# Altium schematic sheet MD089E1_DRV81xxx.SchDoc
size 431 x 279 mm; Date: Not shown in title block; ApprovedBy: Not shown in title block; CheckedBy: Not shown in title block; Author: Not shown in title block; CompanyName: Not shown in title block; DrawnBy: Tilden Chen; Engineer: Not shown in title block; Organization: Not shown in title block; Address1: Not shown in title block; Address2: Not shown in title block; Address3: Not shown in title block; Address4: Not shown in title block; DocumentNumber: 2; Revision: Use project parameter SCH_Rev; SheetNumber: 2; SheetTotal: 3; PageSetup: Record=PageOptions¦CenterHorizontal=True¦CenterVertical=True¦PrintScale=1.00¦XCorrection=1.00¦YCorrection=1.00¦PrintKind=0¦BorderSize=5000000¦LeftOffset=0¦BottomOffset=0¦Orientation=2¦PaperLength=1000¦PaperWidth=1000¦Scale=100¦PaperSource=15¦PrintQuality=600¦MediaType=1¦DitherType=10¦PaperKind=Letter¦PrintScaleMode=1
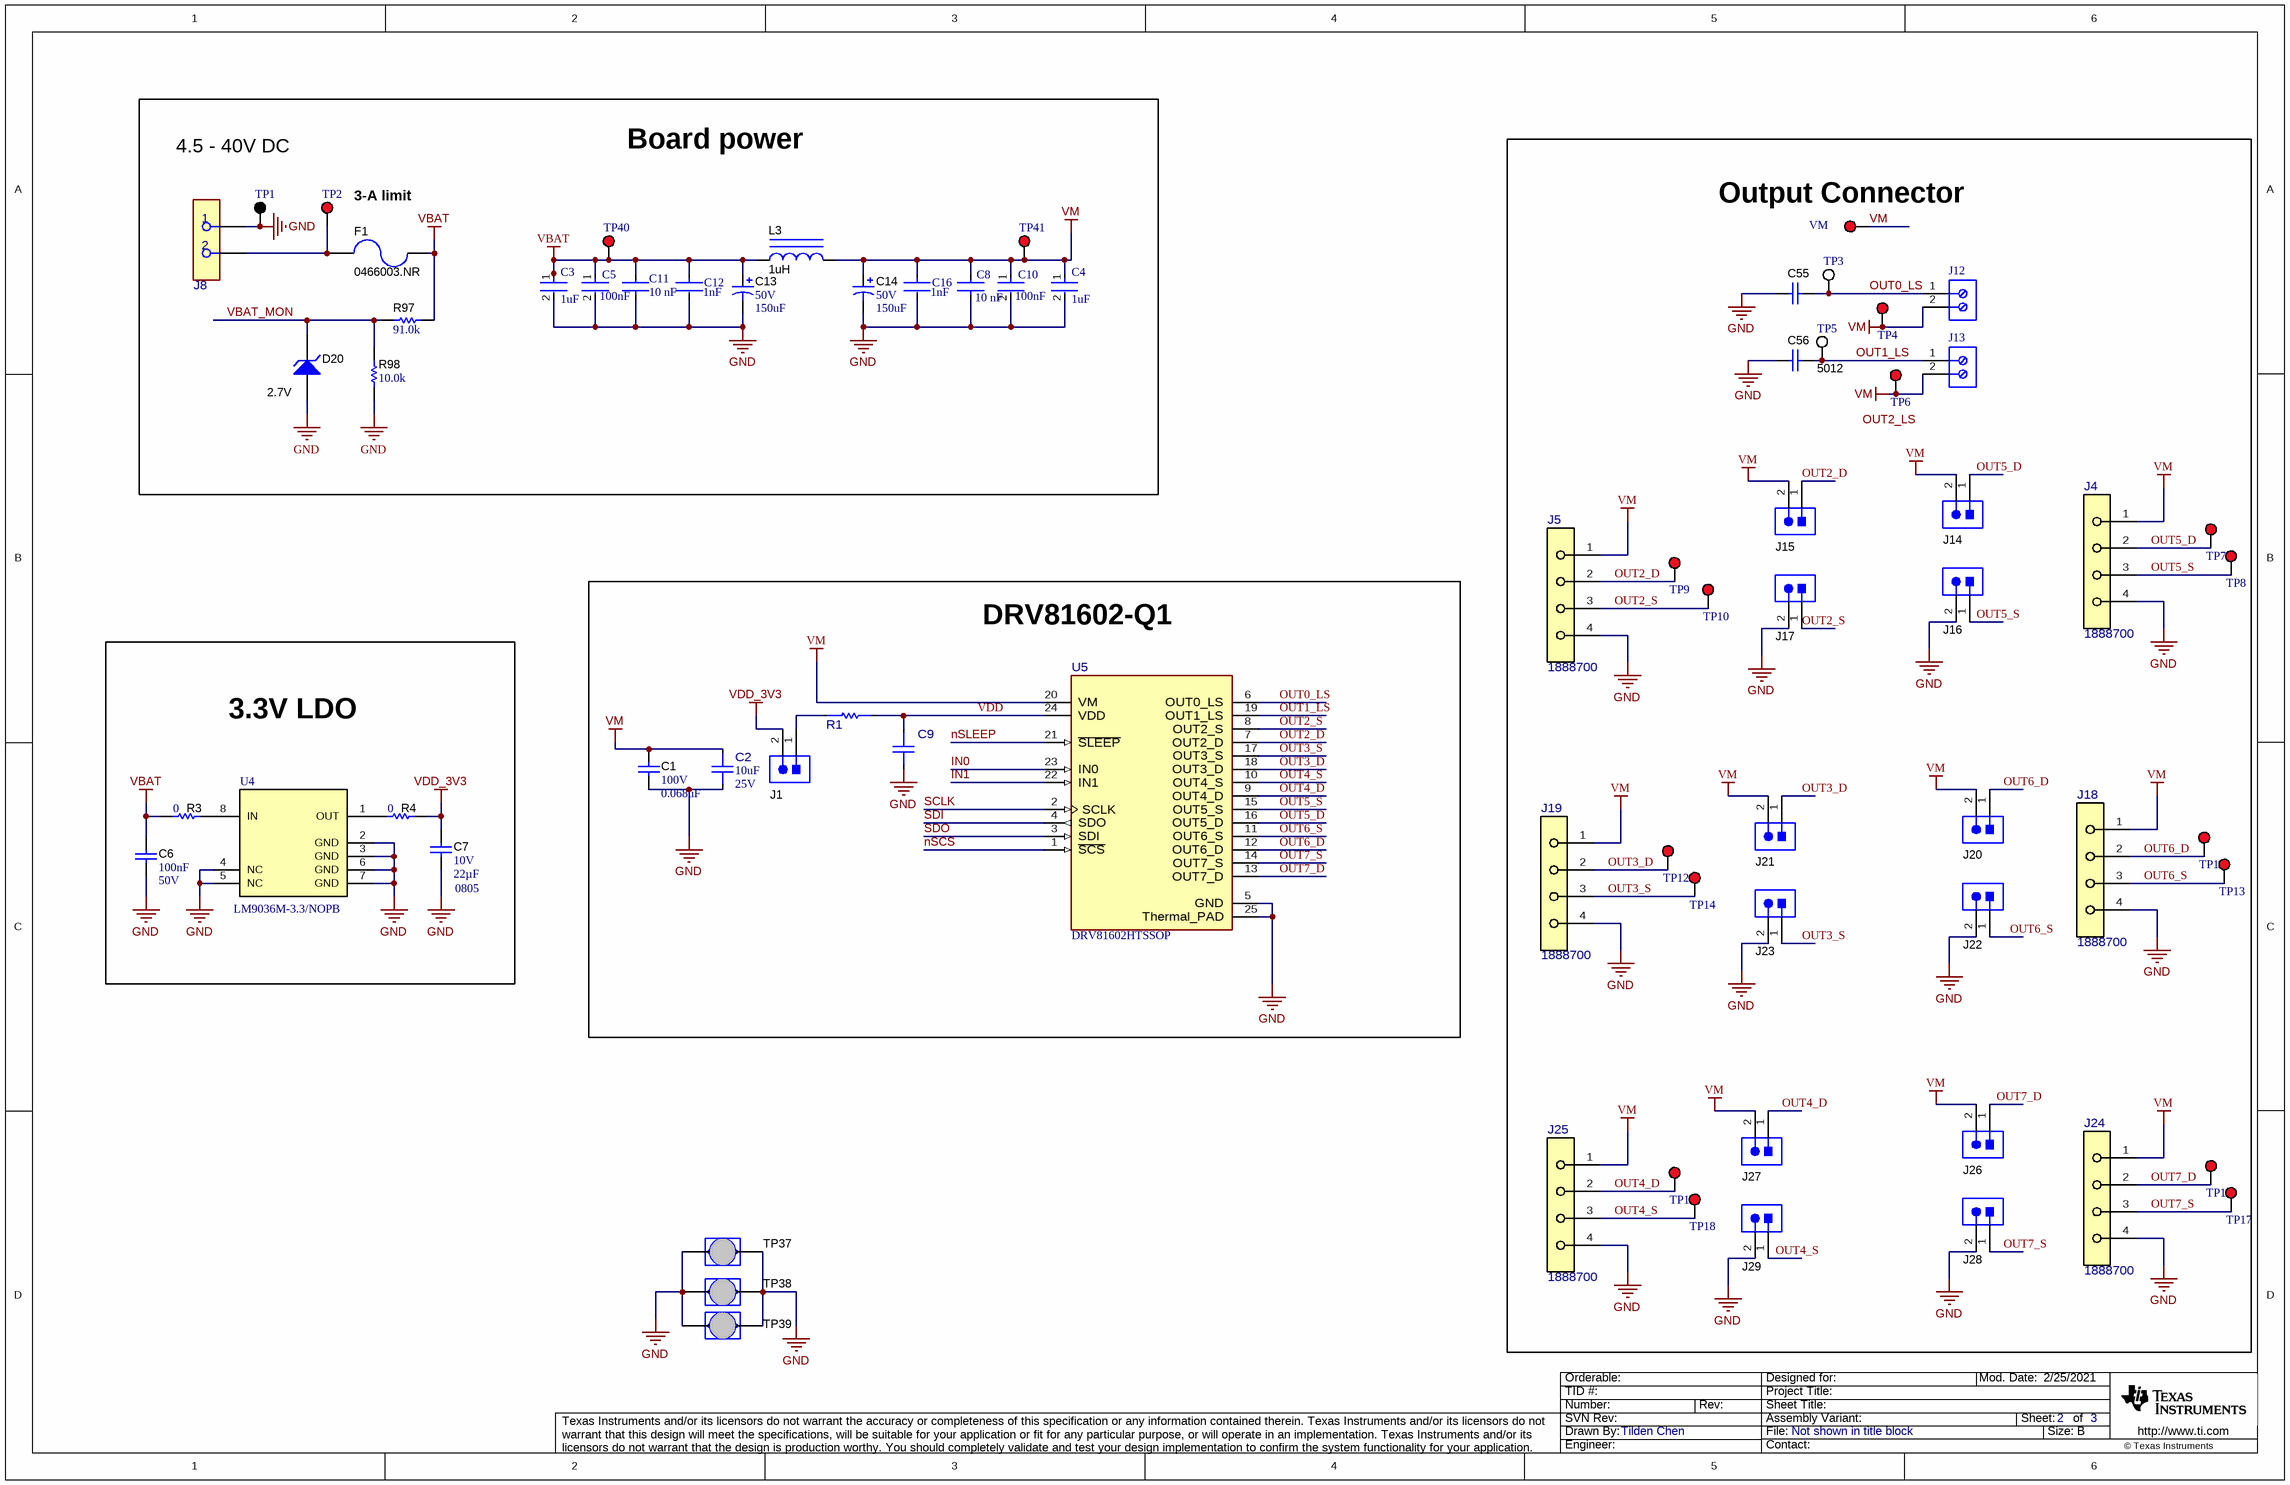
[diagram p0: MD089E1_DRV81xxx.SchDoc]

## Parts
C1  VDC_V: 100V  ValueDisplayed: 0.068uF  [1206]  (hidden comment: 12061C683KAT2A)
C2  ValueDisplayed: 10uF  VDC_V: 25V  [FP-ZRB18AR61E106ME01L_0603-MFG]  (hidden comment: ZRB18AR61E106ME01L)
C3  Capacitance: 1uF  [FP-0603-L_1_6_0_15-W_0_8-IPC_C]  (hidden comment: UMK107AB7105KA-T)
C4  Capacitance: 1uF  [FP-0603-L_1_6_0_15-W_0_8-IPC_C]  (hidden comment: UMK107AB7105KA-T)
C5  value 100nF  [FP-885012206095-MFG]  (hidden comment: 885012206095)
C6  Cap_F: 100nF  VDC_V: 50V  [0603]  (hidden comment: 885012206095)
C7  PackageReference: 0805  VDC_V: 10V  ValueDisplayed: 22µF  [0805_150]  (hidden comment: 885012107011)
C8  value 10 nF  [FP-CC0603-DA-MFG]  (hidden comment: CC0603KPX7R9BB103)
C9  885012205018  [FP-885012205018_0402-MFG]  (value not drawn)
C10  value 100nF  [FP-885012206095-MFG]  (hidden comment: 885012206095)
C11  value 10 nF  [FP-CC0603-DA-MFG]  (hidden comment: CC0603KPX7R9BB103)
C12  1nF  [FP-C0603C-CF-MFG]
C13  VDC_V: 50V  ValueDisplayed: 150uF  [SM_RADIAL_G]  (hidden comment: EEE-FK1H151P)
C14  VDC_V: 50V  ValueDisplayed: 150uF  [SM_RADIAL_G]  (hidden comment: EEE-FK1H151P)
C16  1nF  [FP-C0603C-CF-MFG]
C55  885012206114  [0603]  (value not drawn)
C56  885012206114  [0603]  (value not drawn)
D20  value 2.7V  [SOD-123]  (hidden comment: MMSZ4682-E3-08)
F1  0466003.NR  [1206]
J1  HTSW-102-07-G-S  [Samtec_HTSW-102-07-G-S]  (value not drawn)
J4  1888700  [FP-1888700_HDR4-MFG]
J5  1888700  [FP-1888700_HDR4-MFG]
J8  691250610002  [FP-691250610002_CONN_TERM_BLOCK2-MFG]  (value not drawn)
J12  691101710002  [691101710002]  (value not drawn)
J13  691101710002  [691101710002]  (value not drawn)
J14  HTSW-102-07-G-S  [Samtec_HTSW-102-07-G-S]  (value not drawn)
J15  HTSW-102-07-G-S  [Samtec_HTSW-102-07-G-S]  (value not drawn)
J16  HTSW-102-07-G-S  [Samtec_HTSW-102-07-G-S]  (value not drawn)
J17  HTSW-102-07-G-S  [Samtec_HTSW-102-07-G-S]  (value not drawn)
J18  1888700  [FP-1888700_HDR4-MFG]
J19  1888700  [FP-1888700_HDR4-MFG]
J20  HTSW-102-07-G-S  [Samtec_HTSW-102-07-G-S]  (value not drawn)
J21  HTSW-102-07-G-S  [Samtec_HTSW-102-07-G-S]  (value not drawn)
J22  HTSW-102-07-G-S  [Samtec_HTSW-102-07-G-S]  (value not drawn)
J23  HTSW-102-07-G-S  [Samtec_HTSW-102-07-G-S]  (value not drawn)
J24  1888700  [FP-1888700_HDR4-MFG]
J25  1888700  [FP-1888700_HDR4-MFG]
J26  HTSW-102-07-G-S  [Samtec_HTSW-102-07-G-S]  (value not drawn)
J27  HTSW-102-07-G-S  [Samtec_HTSW-102-07-G-S]  (value not drawn)
J28  HTSW-102-07-G-S  [Samtec_HTSW-102-07-G-S]  (value not drawn)
J29  HTSW-102-07-G-S  [Samtec_HTSW-102-07-G-S]  (value not drawn)
L3  ValueDisplayed: 1uH  [WE-HCC_1210]  (hidden comment: 7443320100)
R1  SG73S1JTTD101J  [FP-SG73S1JTTD101J_0603-MFG]  (value not drawn)
R3  value 0  [0603L]  (hidden comment: Resistor)
R4  value 0  [0603L]  (hidden comment: Resistor)
R97  ValueDisplayed: 91.0k  [0603L]  (hidden comment: RG1608P-913-B-T5)
R98  ValueDisplayed: 10.0k  [0603L]  (hidden comment: RG1608P-103-B-T5)
TP1  5011  [Keystone5011]  (value not drawn)
TP2  5010  [Keystone5010]  (value not drawn)
TP3  5012  [Keystone5012]  (value not drawn)
TP4  5010  [Keystone5010]  (value not drawn)
TP5  5012  [Keystone5012]
TP6  5010  [Keystone5010]  (value not drawn)
TP7  5010  [Keystone5010]  (value not drawn)
TP8  5010  [Keystone5010]  (value not drawn)
TP9  5010  [Keystone5010]  (value not drawn)
TP10  5010  [Keystone5010]  (value not drawn)
TP11  5010  [Keystone5010]  (value not drawn)
TP12  5010  [Keystone5010]  (value not drawn)
TP13  5010  [Keystone5010]  (value not drawn)
TP14  5010  [Keystone5010]  (value not drawn)
TP15  5010  [Keystone5010]  (value not drawn)
TP16  5010  [Keystone5010]  (value not drawn)
TP17  5010  [Keystone5010]  (value not drawn)
TP18  5010  [Keystone5010]  (value not drawn)
TP37  Jumper_2p  [Harwin_D3082-05]  (value not drawn)
TP38  Jumper_2p  [Harwin_D3082-05]  (value not drawn)
TP39  Jumper_2p  [Harwin_D3082-05]  (value not drawn)
TP40  5010  [Keystone5010]  (value not drawn)
TP41  5010  [Keystone5010]  (value not drawn)
U4  LM9036M-3.3/NOPB  [D0008A_N]
U5  DRV81602HTSSOP  [PWP0024T-MFG]
VM  5010  [Keystone5010]  (value not drawn)

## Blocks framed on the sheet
Board power: C3-C5 C8 C10-C14 C16 D20 F1 J8 L3 R97 R98 TP1 TP2 TP40 TP41
Output Connector: C55 C56 J4 J5 J12-J29 TP3-TP18 VM
DRV81602-Q1: C1 C2 C9 J1 R1 U5
3.3V LDO: C6 C7 R3 R4 U4

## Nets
GND: C1.2 C2.2 C3.2 C4.2 C5.2 C6.2 C7.2 C8.1 C9.2 C10.2 C11.1 C12.2 C13.2(-) C14.2(-) C16.2 C55.2 C56.2 D20.2(A) J4.4 J5.4 J8.1 J16.2 J17.2 J18.4 J19.4 J22.2 J23.2 J24.4 J25.4 J28.2 J29.2 R98.1 TP1.1 TP37.1 TP37.2 TP38.1 TP38.2 TP39.1 TP39.2 U4.2(GND) U4.3(GND) U4.4(NC) U4.5(NC) U4.6(GND) U4.7(GND) U5.5(GND) U5.25(Thermal_PAD)
VBAT: C3.1 C5.1 C6.1 C11.2 C12.1 C13.1(+) F1.1 L3.1 R3.2 R97.2 TP40.1
VDD_3V3: C7.1 J1.2 R4.1
VM: C1.1 C2.1 C4.1 C8.2 C10.1 C14.1(+) C16.1 J4.1 J5.1 J12.2 J13.2 J14.2 J15.2 J18.1 J19.1 J20.2 J21.2 J24.1 J25.1 J26.2 J27.2 L3.2 TP4.1 TP6.1 TP41.1 U5.20(VM) VM.1
IN0: U5.23(IN0)
IN1: U5.22(IN1)
nSCS: U5.1(~{SCS})
nSLEEP: U5.21(~{SLEEP})
OUT0_LS: C55.1 J12.1 TP3.1 U5.6(OUT0_LS)
OUT1_LS: C56.1 J13.1 TP5.1 U5.19(OUT1_LS)
OUT2_D: J5.2 J15.1 TP9.1 U5.7(OUT2_D)
OUT2_S: J5.3 J17.1 TP10.1 U5.8(OUT2_S)
OUT3_D: J19.2 J21.1 TP12.1 U5.18(OUT3_D)
OUT3_S: J19.3 J23.1 TP14.1 U5.17(OUT3_S)
OUT4_D: J25.2 J27.1 TP16.1 U5.9(OUT4_D)
OUT4_S: J25.3 J29.1 TP18.1 U5.10(OUT4_S)
OUT5_D: J4.2 J14.1 TP7.1 U5.16(OUT5_D)
OUT5_S: J4.3 J16.1 TP8.1 U5.15(OUT5_S)
OUT6_D: J18.2 J20.1 TP11.1 U5.12(OUT6_D)
OUT6_S: J18.3 J22.1 TP13.1 U5.11(OUT6_S)
OUT7_D: J24.2 J26.1 TP15.1 U5.13(OUT7_D)
OUT7_S: J24.3 J28.1 TP17.1 U5.14(OUT7_S)
SCLK: U5.2(SCLK)
SDI: U5.4(SDO)
SDO: U5.3(SDI)
VBAT_MON: D20.1(K) R97.1 R98.2
VDD: C9.1 R1.2 U5.24(VDD)
NetF1_2: F1.2 J8.2 TP2.1
NetJ1_1: J1.1 R1.1
NetR3_1: R3.1 U4.8(IN)
NetR4_2: R4.2 U4.1(OUT)

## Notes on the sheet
- 4.5 - 40V DC
- 3-A limit
- Labels drawn without touching a wire or pin: OUT2_LS

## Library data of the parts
C1 = CMP-0008507-2: CAP, CERM, 0.068 uF, 100 V, +/- 10%, X7R, 1206; Manufacturer: AVX; TaMin_C: -55°C; ESR_ohm: 0.045; Polarized: N; SizeAreaWB_mm2: 10.92; Value1: 0.045 ohm; U/M: EA; TaMax_C: 125°C; SizeZ_mm: 1.35; SizeX_mm: 3.2; SizeY_mm: 1.6; SizeArea_mm2: 5.12; Cap_F: 68nF; AEC Category: Q200
C2 = CMP-0094458-1: 10µF ±20% 25V Ceramic Capacitor X5R 0603 (1608 Metric); Manufacturer: Murata Electronics; SizeZ_mm: 1.2mm; AEC Qualified: No
C3 C4 = CMP-2000-07531-4: Ceramic Capacitor General Use 1uF ±10% 50V X7R 0603
C5 C10 = CMP-207839-000004-1: CAP CER 0.1UF 50V X7R 0603; Tolerance: 10%
C6 = CMP-0006837-4: CAP, CERM, 0.1 uF, 50 V, +/- 10%, X7R, 0603; Manufacturer: Wurth Elektronik; TaMin_C: -55°C; Polarized: N; SizeAreaWB_mm2: 4.68; Value1: Unknown; U/M: EA; Value: 0.1uF; TaMax_C: 125°C; SizeZ_mm: 1; SizeX_mm: 1.6; SizeY_mm: 0.8; SizeArea_mm2: 1.28; AEC Category: Q200
C7 = CMP-0078153-1: CAP, CERM, 22 µF, 10 V,+/- 20%, X5R, 0805; Manufacturer: Wurth Elektronik; TaMin_C: -55°C; Polarized: N; SizeAreaWB_mm2: 6.75; U/M: EA; Value: 22uF; TaMax_C: 85°C; SizeZ_mm: 1.5; SizeX_mm: 2; SizeY_mm: 1.25; SizeArea_mm2: 2.5; AEC Category: Q200
C8 C11 = CMP-1035-02321-3: CAP CER 10000PF 50V X7R 0603; Manufacturer: YAGEO; Alternative PartNumber: 885382206002; Alternative Manufacturer: Wurth Elektronik; Tolerance: 0.1; Material: Ceramic; Temperature Coefficient: 15%
C9 = CMP-0090362-1: 0.1µF ±10% 10V Ceramic Capacitor X7R 0402 (1005 Metric); Manufacturer: Wurth Electronics; AEC Qualified: No; Value: 100nF; SizeZ_mm: 0.55mm; ValueDisplayed: 100000pF; TempCo: 15%
C12 C16 = CMP-03020-030804-1: CAP CER 1000PF 50V X7R 0603; Manufacturer Part Number: C0603C102J5RACAUTO; Manufacturer: KEMET; Alternate PartNumber: 885012206083; Alternate Manufacturer: Wurth Elektronik; Material: Ceramic; Value: 1,000 pF; Temperature Coefficient: 30ppm/°C; Automotive Grade: Grade 1; Tolerance: 0.05
C13 C14 = CMP-0011178-2: CAP, AL, 150 uF, 50 V, +/- 20%, 0.18 ohm, AEC-Q200 Grade 2, SMD; Manufacturer: Panasonic; Alternate Manufacturer: Wurth Elektronik; Alternate PartNumber: 865080657017; TaMin_C: -55°C; ESR_ohm: 0.18; Polarized: Y; SizeAreaWB_mm2: 172.2; U/M: EA; Value: 150uF; TaMax_C: 105°C; SizeZ_mm: 10.2; SizeX_mm: 12; SizeY_mm: 10.3; Cap_Case: G; SizeArea_mm2: 123.6; CompType: Capacitor; Cap_F: 150µF; IRMS_A: 670mA; AEC Grade: 2; AEC Category: Q200
C55 C56 = CMP-0079993-1: CAP, CERM, 0.01 µF, 100 V,+/- 10%, X7R, 0603; Manufacturer: Wurth Elektronik; TaMin_C: -55°C; Polarized: N; SizeAreaWB_mm2: 4.68; U/M: EA; Value: 0.01uF; TaMax_C: 105°C; SizeZ_mm: 1; SizeX_mm: 1.6; SizeY_mm: 0.8; Value2: 100V; SizeArea_mm2: 1.28; Cap_F: 10nF; AEC Category: Q200; ValueDisplayed: 0.01µF
D20 = CMP-0077592-3: Diode, Zener, 2.7 V, 500 mW, SOD-123; Manufacturer: Vishay-Semiconductor; AEC Category: Q101; AEC Qualified: N; SizeAreaWB_mm2: 13.095; SizeY_mm: 1.7; SizeX_mm: 3.85; Value1: 0.5W; SizeArea_mm2: 6.545; SizeZ_mm: 1.35; RJA_CperW: 340; Power_W: 500mW
F1 = CMP-0084439-1: Fuse, 3 A, 32VAC/VDC, SMD; Manufacturer: Littelfuse; VAC_V: 32V; Rtyp_Ohm: 0.019; Interrupt_AC: 50A; MeltingTyp: 0.576; SizeX_mm: 3.2; Fuse Technology: Board Mount; Irating_A: 3A; SizeAreaWB_mm2: 10.92; TaMin_C: -55°C; Fuse Speed: Fast; SizeArea_mm2: 5.12; SizeY_mm: 1.6; SizeZ_mm: 1.35; TaMax_C: 90°C
J1 J14-J17 J20-J23 J26-J29 = CMP-0075483-1: Header, 100mil, 2x1, Gold, TH; Manufacturer: Samtec; Green_REACh: Passed; CT: False; Green_Lifecycle: Active; CNHeader: True
J4 J5 J18 J19 J24 J25 = CMP-0086377-1: Conn; Term Blk; PCB; Screw; 4; 5.08 mm; Front; 24-14 AWG; 16 A; 250 V; Solder; Manufacturer: Phoenix Contact; ContactFinish: Tin; Current_A: 16A; Row_Count: 1; Voltage_V: 400V
J8 = CMP-0093233-2: 2 Position Wire to Board Terminal Block Horizontal with Board 0.250" (6.35mm) Through Hole; Manufacturer: Wurth Electronics; Current_A: 32A; Conn Gender: Female; Row_Count: 1; ContactFinish: Zinc; SizeZ_mm: 21.6mm; Max Wire Gauge: 10; Min Wire Gauge: 30; Voltage_V: 450V; AEC Qualified: No; Is Female: yes
J12 J13 = CMP-1502-03256-1: Series 101 - 5.00 mm Horizontal Entry Modular with Pressure Clamp WR-TBL, 2 pin; Manufacturer: Wurth Elektronik; Pin Number: 2; Pitch: 5.00mm
L3 = CMP-0063986-1: Inductor, Shielded Drum Core, Ferrite, 1 uH, 24 A, 0.0012 ohm, SMD; Manufacturer: Wurth Elektronik; Isat: 32A @ 30% inductance drop; Irms: 24A @ 50C rise; Green_Lifecycle: Active; SizeAreaWB_mm2: 188.94; DCR_ohm: 1.2m; Green_REACh: Passed; Value: 1uH; Imax_A: 24A; SizeZ_mm: 10; SizeX_mm: 12.1; SizeY_mm: 11.4; SizeArea_mm2: 137.94; Ind_H: 1µH; AEC Category: Q200
R1 = CMP-0095262-1: 100 Ohms ±5% 0.2W, 1/5W Chip Resistor 0603 (1608 Metric) Automotive AEC-Q200, Moisture Resistant, Pulse Withstanding Thick Film; Manufacturer: KOA Speer; AEC Qualified: Yes; Value: 100; AEC Grade: Grade 0; VDC_V: 150V; TaMax_C: +70°C; TempCo: 100ppm/°C; Power_W: 200mW; SizeZ_mm: 0.55mm
R3 R4 = CMP-0025697-4: RES, 0, 5%, 0.1 W, AEC-Q200 Grade 0, 0603; PartNumber: CRCW06030000Z0EA; Manufacturer: Vishay-Dale; Value_Code: 0000; Power_W: 100mW; Value2: 0.1W; VDC_V: 75V; TempCo: 200 ppm/C; EIA_Code: E24; AEC Category: Q200; AEC Qualified: Y; SizeArea_mm2: 1.28; SizeX_mm: 1.6; SizeY_mm: 0.8; SizeZ_mm: 1
R97 = CMP-0023620-3: RES, 91.0 k, 0.1%, 0.1 W, 0603; Manufacturer: Susumu Co Ltd; Power_W: 100mW; TempCo: 25 ppm/C; Value_Code: 91k0; U/M: EA; Value: 91.0k; Res_ohm: 91k; SizeX_mm: 1.6; SizeY_mm: 0.8; SizeZ_mm: 1; Value2: 0.1W; SizeArea_mm2: 1.28; VDC_V: 75V; AEC Category: Q200
R98 = CMP-0023404-3: RES, 10.0 k, 0.1%, 0.1 W, 0603; Manufacturer: Susumu Co Ltd; Power_W: 100mW; TempCo: 25 ppm/C; Value_Code: 10k0; U/M: EA; Value: 10.0k; EIA_Code: E192; Res_ohm: 10k; SizeX_mm: 1.6; SizeY_mm: 0.8; SizeZ_mm: 1; Value2: 0.1W; SizeArea_mm2: 1.28; VDC_V: 75V; AEC Category: Q200
TP1 = CMP-0055148-2: Test Point, Multipurpose, Black, TH; Manufacturer: Keystone Electronics; CNHeader: FALSE; Green_Lifecycle: Active; Green_REACh: Passed; ContactFinish: Silver; CT: TRUE
TP2 TP4 TP6-TP18 VM = CMP-0055147-2: Test Point, Multipurpose, Red, TH; Manufacturer: Keystone Electronics; CNHeader: FALSE; Green_Lifecycle: Active; Green_REACh: Passed; ContactFinish: Silver; CT: TRUE
TP3 TP5 = CMP-0055149-2: Test Point, Multipurpose, White, TH; Manufacturer: Keystone Electronics; ContactFinish: Silver; CT: TRUE; CNHeader: FALSE; Green_Lifecycle: Active; Green_REACh: Passed
TP37-TP39 = CMP-0075110-1: 1mm Uninsulated Shorting Plug, 10.16mm spacing, TH; Manufacturer: Harwin; PartNumber: D3082-05; CompType: Jumper Wire; CNHeader: False; Green_Lifecycle: Active; Green_REACh: Passed
TP40 TP41 = CMP-0055147-1: Test Point, Multipurpose, Red, TH; Manufacturer: Keystone; CNHeader: FALSE; Green_Lifecycle: Active; Green_REACh: Passed; ContactFinish: Silver; CT: TRUE
U4 = CMP-0070570-1: Ultra-Low Quiescent Current Voltage Regulator, 8-pin Narrow SOIC, Pb-Free; Manufacturer: Texas Instruments; PackageTopMarking: NSZXTT*LM903*6M-3; PowerWise: N; CompType: LDO IC
U5 = CMP-0120420-1: 8-channel Configurable Low-side and High-side Driver for Automotive Relay, Lighting and Motor Control; Manufacturer: Texas Instruments; SizeZ_mm: 1.2mm; AEC Qualified: No; Max Supply Voltage: 40V; Min Supply Voltage: 3V; Number Of Outputs: 8; Standoff Height: 0.05mm; TaMax_C: +125°C; TaMin_C: -40°C; TJmax_C: +150°C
